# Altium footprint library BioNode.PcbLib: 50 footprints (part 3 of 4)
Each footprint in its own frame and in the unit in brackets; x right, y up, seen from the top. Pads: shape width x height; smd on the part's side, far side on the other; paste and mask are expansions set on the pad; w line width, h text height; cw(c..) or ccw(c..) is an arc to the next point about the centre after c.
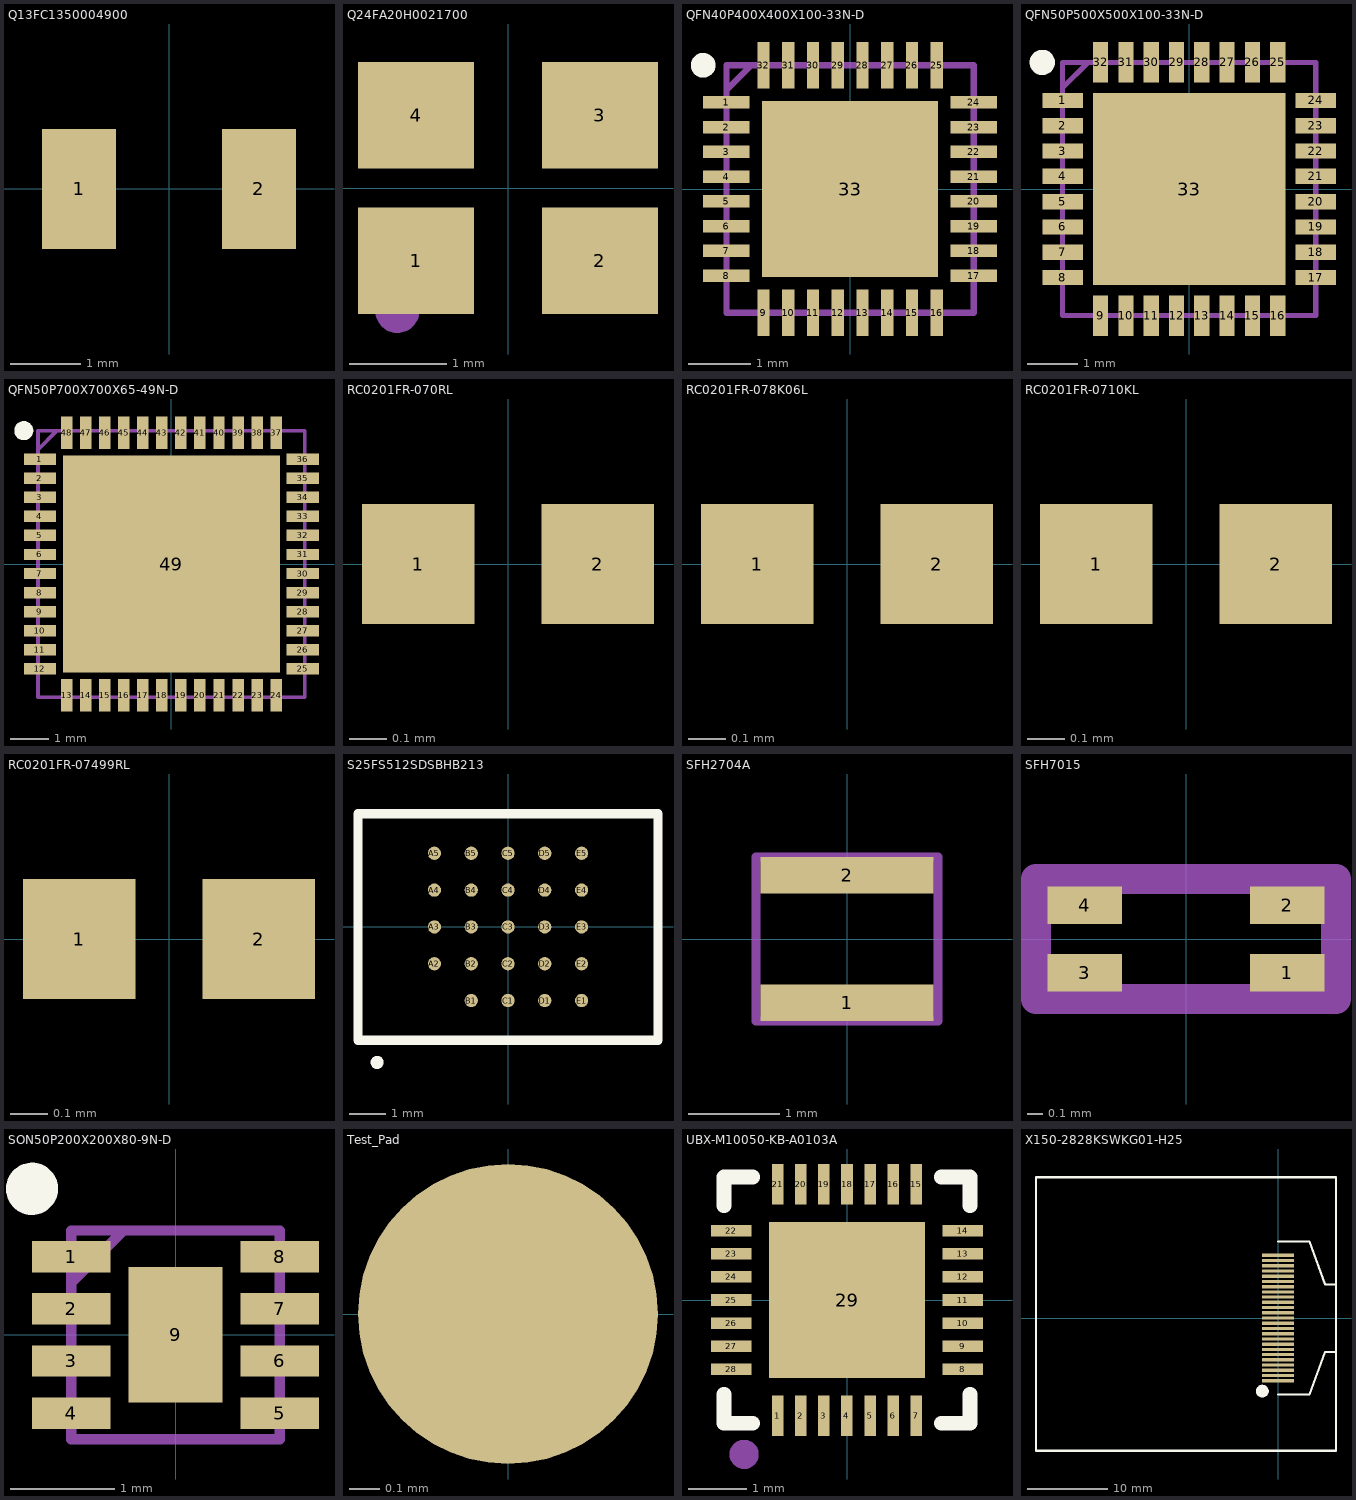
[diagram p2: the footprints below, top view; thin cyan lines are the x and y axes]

## Q13FC1350004900 [mm]
pads (2):
  rect 1.05x1.7 smd: 1(-1.275,0) 2(1.275,0)
3D body "Q13FC1350004900.step": height 0.9, standoff -0.01, extent -1.6,-0.75 1.6,0.75

## Q24FA20H0021700 [mm]
pads (4):
  rect 1.2x1.1 smd: 1(-0.95,-0.75) 2(0.95,-0.75) 3(0.95,0.75) 4(-0.95,0.75)
Mechanical 6:
  circle w0.254: c-1.143,-1.27 r0.1
3D body "Q24FA20H0021700.step": height 0.56, standoff -0.01, extent -1.25,-1 1.25,1

## QFN40P400X400X100-33N-D [mm]
pads (33):
  rect 0.75x0.2 smd: 1(-2,1.4) 2(-2,1) 3(-2,0.6) 4(-2,0.2) 5(-2,-0.2) 6(-2,-0.6) 7(-2,-1) 8(-2,-1.4) 17(2,-1.4) 18(2,-1) 19(2,-0.6) 20(2,-0.2) 21(2,0.2) 22(2,0.6) 23(2,1) 24(2,1.4)
  rect 0.2x0.75 smd: 9(-1.4,-2) 10(-1,-2) 11(-0.6,-2) 12(-0.2,-2) 13(0.2,-2) 14(0.6,-2) 15(1,-2) 16(1.4,-2) 25(1.4,2) 26(1,2) 27(0.6,2) 28(0.2,2) 29(-0.2,2) 30(-0.6,2) 31(-1,2) 32(-1.4,2)
  rect 2.85x2.85 smd: 33(0,0)
Top Overlay:
  circle w0.2: c-2.375,2 r0.1
Mechanical 13:
  lines w0.1: -2,1.6 -1.6,2 ; -2,-2 2,-2 2,2 -2,2 -2,-2
3D body "ADS1292IRSMR.stp": height 1, standoff 0, extent -2,-2 2,2

## QFN50P500X500X100-33N-D [mm]
pads (33):
  rect 0.8x0.3 smd: 1(-2.5,1.75) 2(-2.5,1.25) 3(-2.5,0.75) 4(-2.5,0.25) 5(-2.5,-0.25) 6(-2.5,-0.75) 7(-2.5,-1.25) 8(-2.5,-1.75) 17(2.5,-1.75) 18(2.5,-1.25) 19(2.5,-0.75) 20(2.5,-0.25) 21(2.5,0.25) 22(2.5,0.75) 23(2.5,1.25) 24(2.5,1.75)
  rect 0.3x0.8 smd: 9(-1.75,-2.5) 10(-1.25,-2.5) 11(-0.75,-2.5) 12(-0.25,-2.5) 13(0.25,-2.5) 14(0.75,-2.5) 15(1.25,-2.5) 16(1.75,-2.5) 25(1.75,2.5) 26(1.25,2.5) 27(0.75,2.5) 28(0.25,2.5) 29(-0.25,2.5) 30(-0.75,2.5) 31(-1.25,2.5) 32(-1.75,2.5)
  rect 3.8x3.8 smd: 33(0,0)
Top Overlay:
  circle w0.25: c-2.9,2.5 r0.125
Mechanical 13:
  lines w0.1: -2.5,2 -2,2.5 ; -2.5,-2.5 2.5,-2.5 2.5,2.5 -2.5,2.5 -2.5,-2.5
3D body "LR1121IMLTRT.stp": height 1, standoff 0, extent -2.55,-2.55 2.55,2.55

## QFN50P700X700X65-49N-D [mm]
pads (49):
  rect 0.85x0.3 smd: 1(-3.45,2.75) 2(-3.45,2.25) 3(-3.45,1.75) 4(-3.45,1.25) 5(-3.45,0.75) 6(-3.45,0.25) 7(-3.45,-0.25) 8(-3.45,-0.75) 9(-3.45,-1.25) 10(-3.45,-1.75) 11(-3.45,-2.25) 12(-3.45,-2.75) 25(3.45,-2.75) 26(3.45,-2.25) 27(3.45,-1.75) 28(3.45,-1.25) 29(3.45,-0.75) 30(3.45,-0.25) 31(3.45,0.25) 32(3.45,0.75) 33(3.45,1.25) 34(3.45,1.75) 35(3.45,2.25) 36(3.45,2.75)
  rect 0.3x0.85 smd: 13(-2.75,-3.45) 14(-2.25,-3.45) 15(-1.75,-3.45) 16(-1.25,-3.45) 17(-0.75,-3.45) 18(-0.25,-3.45) 19(0.25,-3.45) 20(0.75,-3.45) 21(1.25,-3.45) 22(1.75,-3.45) 23(2.25,-3.45) 24(2.75,-3.45) 37(2.75,3.45) 38(2.25,3.45) 39(1.75,3.45) 40(1.25,3.45) 41(0.75,3.45) 42(0.25,3.45) 43(-0.25,3.45) 44(-0.75,3.45) 45(-1.25,3.45) 46(-1.75,3.45) 47(-2.25,3.45) 48(-2.75,3.45)
  rect 5.7x5.7 smd: 49(0,0)
Top Overlay:
  circle w0.25: c-3.875,3.5 r0.125
Mechanical 13:
  lines w0.1: -3.5,3 -3,3.5 ; -3.5,-3.5 3.5,-3.5 3.5,3.5 -3.5,3.5 -3.5,-3.5
3D body "STM32WBA52CGU6.stp": height 0.65, standoff 0, extent -3.55,-3.55 3.55,3.55

## RC0201FR-070RL [mm]
pads (2):
  rect 0.303x0.324 smd: 1(-0.242,0) 2(0.242,0)
3D body "RC0201FR-078K06L.step": height 0.24, standoff 0, extent -0.3,-0.15 0.3,0.151

## RC0201FR-078K06L [mm]
pads (2):
  rect 0.303x0.324 smd: 1(-0.242,0) 2(0.242,0)
3D body "RC0201FR-078K06L.step": height 0.24, standoff 0, extent -0.3,-0.15 0.3,0.151

## RC0201FR-0710KL [mm]
pads (2):
  rect 0.303x0.324 smd: 1(-0.242,0) 2(0.242,0)
3D body "RC0201FR-078K06L.step": height 0.24, standoff 0, extent -0.3,-0.15 0.3,0.151

## RC0201FR-07499RL [mm]
pads (2):
  rect 0.303x0.324 smd: 1(-0.242,0) 2(0.242,0)
3D body "RC0201FR-078K06L.step": height 0.24, standoff 0, extent -0.3,-0.15 0.3,0.151

## S25FS512SDSBHB213 [mm]
pads (24):
  rrect100% 0.36x0.36 smd: A2(-2,-1) A3(-2,0) A4(-2,1) A5(-2,2) B1(-1,-2) B2(-1,-1) B3(-1,0) B4(-1,1) B5(-1,2) C1(0,-2) C2(0,-1) C3(0,0) C4(0,1) C5(0,2) D1(1,-2) D2(1,-1) D3(1,0) D4(1,1) D5(1,2) E1(2,-2) E2(2,-1) E3(2,0) E4(2,1) E5(2,2)
Top Overlay:
  circle w0.254: c-3.556,-3.683 r0.05
  lines w0.254: -4.076,-3.076 4.076,-3.076 4.076,3.076 -4.076,3.076 -4.076,-3.076
3D body "S25FS512SDSBHB213.step": height 1.01, standoff 0, extent -4,-3 4,3

## SFH2704A [mm]
pads (2):
  rect 1.9x0.4 smd: 1(0,-0.7) 2(0,0.7)
Mechanical 13:
  lines w0.1: -1,-0.9 -1,0.9 1,0.9 1,-0.9 -1,-0.9
3D body "SFH_2704A.stp": height 0.6, standoff 0, extent -1,-0.9 1,0.9

## SFH7015 [mm]
pads (4):
  rect 0.5x0.25 smd: 1(0.675,-0.225) 2(0.675,0.225) 3(-0.675,-0.225) 4(-0.675,0.225)
Mechanical 13:
  lines w0.2: -1,-0.4 -1,0.4 1,0.4 1,-0.4 -1,-0.4
3D body "SFH_7015.stp": height 0.4, standoff -0.2, extent -1,-0.4 1,0.4

## SON50P200X200X80-9N-D [mm]
pads (9):
  rect 0.75x0.3 smd: 1(-1,0.75) 2(-1,0.25) 3(-1,-0.25) 4(-1,-0.75) 5(1,-0.75) 6(1,-0.25) 7(1,0.25) 8(1,0.75)
  rect 0.9x1.3 smd: 9(0,0)
Top Overlay:
  circle w0.25: c-1.375,1.4 r0.125
Mechanical 13:
  lines w0.1: -1,0.5 -0.5,1 ; -1,-1 -1,1 1,1 1,-1 -1,-1
3D body "MAX17048G+T10.stp": height 0.8, standoff 0, extent -1.05,-1 1.05,1

## Test_Pad [mm]
pads (1):
  round 1 smd: ""(0,0)

## UBX-M10050-KB-A0103A [mm]
pads (29):
  rect 0.2x0.7 smd: 1(-1.2,-2) 2(-0.8,-2) 3(-0.4,-2) 4(-0.001,-2) 5(0.4,-2) 6(0.8,-2) 7(1.2,-2) 15(1.2,2) 16(0.8,2) 17(0.4,2) 18(0,2) 19(-0.4,2) 20(-0.8,2) 21(-1.2,2)
  rect 0.7x0.2 smd: 8(2,-1.2) 9(2,-0.8) 10(2,-0.4) 11(1.999,0) 12(2,0.4) 13(2,0.8) 14(2,1.2) 22(-2,1.2) 23(-2,0.8) 24(-2,0.4) 25(-2,0) 26(-2,-0.4) 27(-2,-0.8) 28(-2,-1.2)
  rect 2.7x2.7 smd: 29(0,0)
Top Overlay:
  lines w0.254: -2.127,-1.627 -2.127,-2.127 -1.627,-2.127 ; -2.127,1.627 -2.127,2.127 -1.627,2.127 ; 1.627,-2.127 2.127,-2.127 2.127,-1.627 ; 1.627,2.127 2.127,2.127 2.127,1.627
Mechanical 6:
  circle w0.254: c-1.778,-2.667 r0.125
  region: -1.587,-2.603 -1.547,-2.698 -1.587,-2.794 -1.682,-2.834 -1.778,-2.794 -1.818,-2.698 -1.778,-2.603 -1.682,-2.563
3D body "UBX-M10050-KB-A0103A.step": height 0.73, standoff -0.03, extent -2.01,-2.01 2.01,2.01

## X150-2828KSWKG01-H25 [mm]
pads (25):
  rect 4x0.4 smd: 1(0,-7.8) 2(0,-7.15) 3(0,-6.5) 4(0,-5.85) 5(0,-5.2) 6(0,-4.55) 7(0,-3.9) 8(0,-3.25) 9(0,-2.6) 10(0,-1.95) 11(0,-1.3) 12(0,-0.65) 13(0,0) 14(0,0.65) 15(0,1.3) 16(0,1.95) 17(0,2.6) 18(0,3.25) 19(0,3.9) 20(0,4.55) 21(0,5.2) 22(0,5.85) 23(0,6.5) 24(0,7.15) 25(0,7.8)
Top Overlay:
  region: -1.759,-8.347 -1.638,-8.388 -1.525,-8.449 -1.424,-8.528 -1.337,-8.623 -1.267,-8.73 -1.215,-8.848 -1.184,-8.972 -1.173,-9.1 -1.184,-9.228 -1.215,-9.352 -1.267,-9.47 -1.337,-9.577 -1.424,-9.672 -1.525,-9.75 -1.638,-9.812 -1.759,-9.853 -1.886,-9.874 -2.014,-9.874 -2.141,-9.853 -2.262,-9.812 -2.375,-9.75 -2.476,-9.672 -2.563,-9.577 -2.633,-9.47 -2.685,-9.352 -2.716,-9.228 -2.727,-9.1 -2.716,-8.972 -2.685,-8.848 -2.633,-8.73 -2.563,-8.623 -2.476,-8.528 -2.375,-8.449 -2.262,-8.388 -2.141,-8.347 -2.014,-8.326 -1.886,-8.326
  lines w0.254: 1.586,-9.5 0.016,-9.5 ; 1.637,9.5 0,9.5 3.9,9.5 5.85,4.2 7.2,4.194 ; 3.266,-9.5 0.016,-9.5 ; 7.2,-4.213 5.85,-4.2 3.916,-9.5 0.016,-9.5 ; -30.1,-16.5 -30.1,17.5 7.2,17.5 7.2,-16.5 -30.1,-16.5
3D body "X150-2828KSWKG01-H25.step": height 1.25, standoff -0.21, extent -31.371,-16.95 7.239,16.95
